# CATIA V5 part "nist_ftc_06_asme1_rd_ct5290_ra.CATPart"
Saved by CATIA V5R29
Part number: NIST PMI FTC 06 ASME1
Revision: D
Description: NIST PMI test model downloaded from http://go.usa.gov/mGVm
Bounding box of the stored display mesh (mm): x -152.4 to 152.4, y 0 to 97.79, z -247.65 to 0
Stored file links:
  E:\users\dgn\TPS V5\Import-export annotations\Step\PMI representation 2015\NIST UC\FTC\R29\nist_ftc_06_asme1_ct5240_rd - V5R29.CATPart
  E:\users\dgn\TPS V5\Import-export annotations\Step\PMI representation 2015\NIST UC\nist_ftc_06_asme1_ct5240_rd.CATPart
  E:\users\dgn\TPS V5\Import-export annotations\Step\PMI representation 2015\NIST UC\CVDHoleParallelCountersink_1_TAG.CATPart
  E:\users\dgn\TPS V5\Import-export annotations\Step\PMI representation 2015\NIST UC\TS_CounterboredHole.CATPart
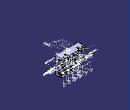
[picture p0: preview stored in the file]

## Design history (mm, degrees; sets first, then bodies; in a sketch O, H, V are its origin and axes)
TTRSSet1
f4a2d38f3ddc11d3a929006094b99c4b_11 "CATTPSSet"
Set1 "Geom_for_MBD_A_notes"
  Plane1: type Equation, A -0.57735, B -0.57735, C 0.57735, Length 229.55, RefPoint vertex [face of Pad1 from Sketch12.L1 | face of Pad1 from Sketch12.L2 | end face of Pad1], RefAxis AxisSystem5
Set2 "MBD_A"
  AxisSystem1 "F1": origin (108.585, 50.8, -209.55), X (-1, 0, 0), Y (0, 1, 0), Z (0, 0, -1)
  AxisSystem2 "F2": origin (36.195, 50.8, -209.55), X (-1, 0, 0), Y (0, 1, 0), Z (0, 0, -1)
  AxisSystem3 "F3": origin (-36.195, 50.8, -209.55), X (-1, 0, 0), Y (0, 1, 0), Z (0, 0, -1)
  AxisSystem4 "F4": origin (-108.585, 50.8, -209.55), X (-1, 0, 0), Y (0, 1, 0), Z (0, 0, -1)
  AxisSystem5 "EAB": origin (0, 0, -209.55), X (-1, 0, 0), Y (0, 0, 1), Z (0, 1, 0)
Set3 "MBD_C"
  AxisSystem6 "DCJ": origin (82.55, 31.75, 0), X (1, 0, 0), Y (0, 0, -1), Z (0, 1, 0)
  AxisSystem7 "DCK": origin (-82.55, 31.75, 0), X (1, 0, 0), Y (0, 0, -1), Z (0, 1, 0)
  AxisSystem8 "DG": origin (76.2, 31.75, -158.75), X (0, 0, -1), Y (-1, 0, 0), Z (0, 1, 0)
  AxisSystem9 "DH": origin (-76.2, 31.75, -158.75), X (0, 0, -1), Y (-1, 0, 0), Z (0, 1, 0)
  Sketch1 on face of Pocket1 from Sketch15.L6, origin (-87.885, 40.9814, 0), H (-0.4226, -0.9063, 0), V (0, 0, 1)
    line L1 (-45.8598, -31.75) -> (-45.8598, 0)
    point P1 (-45.8598, -31.75)
    reference projected point E1 (-45.8598, -31.75) from Sketch10.P5
    vertical: L1 V
    coincidence: P1 E1
  Sketch2 on face of RectPattern2, origin (87.885, 40.9814, 0), H (-0.4226, 0.9063, 0), V (0, 0, 1)
    line L1 (45.8598, -31.75) -> (45.8598, 0)
    point P1 (45.8598, -31.75)
    reference projected point E1 (45.8598, -31.75) from Sketch9.P6
    vertical: L1 V
    coincidence: P1 E1
  Sketch3 on face of RectPattern2, origin (47.7271, -22.2555, 0), H (-0.4226, -0.9063, 0), V (0, 0, 1)
    line L1 (-115.6341, -31.75) -> (-115.6341, 0)
    point P1 (-115.6341, -31.75)
    reference projected point E1 (-115.6341, -31.75) from Sketch9.P5
    vertical: L1 V
    coincidence: P1 E1
  Sketch4 on Plane6, origin (0, 66.04, 0), H (-1, 0, 0), V (0, 0, 1)
    circle A1 centre (76.2, -158.75) radius 12.7
    point P1 (76.2, -158.75)
    reference projected point E1 (76.2, -158.75) from axis of face of RectPattern6
    circle A2 centre (-76.2, -158.75) radius 12.7
    point P2 (-76.2, -158.75)
    reference projected point E2 (-76.2, -158.75) from axis of face of Hole3
    radius A1 = 12.7
    radius A2 = 12.7
    coincidence: E1 P1, E2 P2
  Sketch5 on face of RectPattern2, origin (47.7271, -22.2555, 0), H (-0.4226, -0.9063, 0), V (0, 0, 1)
    projected line E1 (-132.4556, 0) -> (-97.4233, 0) from edge [face of RectPattern2 | face of Pad1 from Sketch12.L1]
    projected line E2 (-132.4556, -31.75) -> (-97.4233, -31.75) from edge [face of Pad1 from Sketch12.L7 | face of RectPattern2]
    line L1 (-97.4233, 0) -> (-115.6341, 0)
    point P5 (-114.9395, 0)
    line L2 (-115.6341, -31.75) -> (-97.4233, -31.75)
    point P6 (-115.6341, -31.75)
    line L3 (-97.4233, 0) -> (-97.4233, -31.75)
    line L4 (-115.6341, 0) -> (-115.6341, -31.75)
    reference projected line E3 (-115.6341, -31.75) -> (-115.6341, 0) from Sketch3
    midpoint: P5 E1
    horizontal: L1 H, L2 H
    coincidence: P6 E2, E3 L4
    vertical: L3 V, L4 V
  Sketch6 on face of RectPattern2, origin (87.885, 40.9814, 0), H (-0.4226, 0.9063, 0), V (0, 0, 1)
    projected line E1 (62.6813, 0) -> (27.6491, 0) from edge [face of Pad1 from Sketch12.L1 | face of RectPattern2]
    projected line E2 (45.8598, 0) -> (27.6491, 0) from edge [face of Pad1 from Sketch12.L1 | face of RectPattern2]
    projected line E3 (27.6491, -31.75) -> (27.6491, 0) from edge [face of RectPattern2 | face of RectPattern2]
    projected line E4 (27.6491, -31.75) -> (62.6813, -31.75) from edge [face of Pad1 from Sketch12.L7 | face of RectPattern2]
    projected line E5 (27.6491, -31.75) -> (45.8598, -31.75) from edge [face of Pad1 from Sketch12.L7 | face of RectPattern2]
    projected line E6 (45.8598, -31.75) -> (45.8598, 0) from Sketch2.L1
  Sketch7 on face of Pocket1 from Sketch15.L6, origin (-87.885, 40.9814, 0), H (-0.4226, -0.9063, 0), V (0, 0, 1)
    projected line E1 (-62.6813, 0) -> (-27.6491, 0) from edge [face of Pocket1 from Sketch15.L6 | face of Pad1 from Sketch12.L1]
    projected line E2 (-45.8598, 0) -> (-27.6491, 0) from edge [face of Pocket1 from Sketch15.L6 | face of Pad1 from Sketch12.L1]
    projected line E3 (-62.6813, -31.75) -> (-27.6491, -31.75) from edge [face of Pad1 from Sketch12.L7 | face of Pocket1 from Sketch15.L6]
    projected line E4 (-45.8598, -31.75) -> (-27.6491, -31.75) from edge [face of Pad1 from Sketch12.L7 | face of Pocket1 from Sketch15.L6]
    projected line E5 (-27.6491, -31.75) -> (-27.6491, 0) from edge [face of Pocket1 from Sketch15.L5 | face of Pocket1 from Sketch15.L6]
    projected line E6 (-45.8598, -31.75) -> (-45.8598, 0) from Sketch1.L1
  Sketch8 on face of Pocket1 from Sketch15.L1, origin (-47.7271, -22.2555, 0), H (-0.4226, 0.9063, 0), V (0, 0, 1)
    projected line E1 (97.4233, -31.75) -> (132.4556, -31.75) from edge [face of Pad1 from Sketch12.L7 | face of Pocket1 from Sketch15.L1]
    projected line E2 (97.4233, -31.75) -> (115.6341, -31.75) from edge [face of Pad1 from Sketch12.L7 | face of Pocket1 from Sketch15.L1]
    projected line E3 (97.4233, -31.75) -> (97.4233, 0) from edge [face of Pocket1 from Sketch15.L1 | face of Pocket1 from Sketch15.L2]
    projected line E4 (132.4556, 0) -> (97.4233, 0) from edge [face of Pad1 from Sketch12.L1 | face of Pocket1 from Sketch15.L1]
    projected line E5 (115.6341, 0) -> (97.4233, 0) from edge [face of Pad1 from Sketch12.L1 | face of Pocket1 from Sketch15.L1]
    projected line E6 (115.6341, -31.75) -> (115.6341, 0) from Sketch11.L1
    construction line L1 through (0, 0) direction (0, 1)
  Sketch9 on face of Pad1 from Sketch12.L7, origin (0, 0, -31.75), H (1, 0, 0), V (0, -1, 0)
    projected line E1 (103.7053, -97.79) -> (88.9, -66.04) from edge [face of Pad1 from Sketch12.L7 | face of RectPattern2]
    projected line E2 (76.2, -66.04) -> (61.3947, -97.79) from edge [face of Pad1 from Sketch12.L7 | face of RectPattern2]
    line L1 (88.9, -66.04) -> (76.2, -66.04)
    line L2 (96.5962, -82.5446) -> (68.5038, -82.5446)
    point P5 (96.5962, -82.5446)
    point P6 (68.5038, -82.5446)
    point P7 (96.5962, -82.5446)
    point P8 (68.5038, -82.5446)
    length L2 = 28.0924
    horizontal: L1 H, L2 H
    coincidence: P5 E1, P6 E2, P7 P5, P8 P6
  Sketch10 on face of Pad1 from Sketch12.L7, origin (0, 0, -31.75), H (1, 0, 0), V (0, -1, 0)
    projected line E1 (-61.3947, -97.79) -> (-76.2, -66.04) from edge [face of Pad1 from Sketch12.L7 | face of Pocket1 from Sketch15.L6]
    projected line E2 (-88.9, -66.04) -> (-103.7053, -97.79) from edge [face of Pad1 from Sketch12.L7 | face of Pocket1 from Sketch15.L1]
    line L1 (-76.2, -66.04) -> (-88.9, -66.04)
    line L2 (-68.5038, -82.5446) -> (-96.5962, -82.5446)
    point P5 (-68.5038, -82.5446)
    point P6 (-96.5962, -82.5446)
    point P7 (-68.5038, -82.5446)
    point P8 (-96.5962, -82.5446)
    length L2 = 28.0924
    horizontal: L1 H, L2 H
    coincidence: P5 E1, P7 P5, P6 E2, P8 P6
  Sketch11 on face of Pocket1 from Sketch15.L1, origin (-47.7271, -22.2555, 0), H (-0.4226, 0.9063, 0), V (0, 0, 1)
    line L1 (115.6341, -31.75) -> (115.6341, 0)
    point P1 (115.6341, -31.75)
    reference projected point E1 (115.6341, -31.75) from Sketch10.P6
    vertical: L1 V
    coincidence: P1 E1
Set4 "MBD_A_B_C"
  AxisSystem10 "DBC": origin (0, 31.75, 0), X (1, 0, 0), Y (0, 0, -1), Z (0, 1, 0)
  AxisSystem11 "ABC": origin (0, 0, 0), X (1, 0, 0), Y (0, 0, -1), Z (0, 1, 0)
Set5
  Plane2: type Offset, RefPlane xy-plane, Offset 247.65, reversed
  Plane3: type Offset, RefPlane zx-plane, Offset 46.99
  Plane4: type Offset, RefPlane yz-plane, Offset 76.2
  Plane5: type Offset, RefPlane yz-plane, Offset 114.3
  Point1: type OnCurve, Support edge [face of Pad1 from Sketch12.L7 | face of Pocket1 from Sketch15.L1], Length 18.2093
  Point2: type OnCurve, Support edge [face of Pad1 from Sketch12.L7 | face of Pocket1 from Sketch15.L6], Length 18.2093
  Point3: type OnCurve, Support edge [face of Pad1 from Sketch12.L7 | face of RectPattern2], Length 18.2093
  Point4: type OnCurve, Support edge [face of Pad1 from Sketch12.L7 | face of RectPattern2], Length 18.2093
  Plane6: type Offset, RefPlane zx-plane, Offset 66.04
  Plane7: type Angle, RefPlane xy-plane, Direction edge [face of Pad1 from Sketch12.L2 | face of Pad1 from Sketch12.L1], Angle 45
  Point5: type OnCurve, Support edge [face of Pad1 from Sketch12.L2 | face of Pad1 from Sketch12.L1], Length 152.4
  Point6: type OnPlane, Support face of Pad1 from Sketch12.L6, H 0, V 0, Direction (-1, 0, 0)
  Point7: type OnCurve, Support edge [face of Fillet1 | face of Pad1 from Sketch12.L6], RefPoint {extremum Reference edge [face of Fillet1 | face of Pad1 from Sketch12.L6], Direction (1, 2, 3)}, Length 65.977
  Point8: type OnCurve, Support edge [face of Fillet1 | face of Pad1 from Sketch12.L6], RefPoint {extremum Reference edge [face of Fillet1 | face of Pad1 from Sketch12.L6], Direction (1, 2, 3)}, Length 65.9892
  Point9: type OnPlane, Support face of Pad1 from Sketch12.L1, H 82.55, V 31.75, Direction (1, 0, 0)
  Point10: type OnPlane, Support face of Pad1 from Sketch12.L1, H -82.55, V 31.75, Direction (1, 0, 0)
  Plane8: type Offset, RefPlane face of Pad1 from Sketch12.L2, Offset 82.55
  Plane9: type Offset, RefPlane face of Pad1 from Sketch12.L2, Offset 66.04
  Point11: type OnSurface, Support face of Fillet1, Length 0, Direction (-0.9567, 0.021, -0.2904)
  Plane10: type Offset, RefPlane face of Pad1 from Sketch12.L1, Offset 107.95
  Point12: type OnPlane, Support face of Pad1 from Sketch12.L6, H -76.2, V -158.75, Direction (-1, 0, 0)
  Point13: type OnPlane, Support face of Pad1 from Sketch12.L6, H 76.2, V -158.75, Direction (-1, 0, 0)
  Point14: type OnPlane, Support face of Pad1 from Sketch12.L2, H 0, V -209.55, Direction (1, 0, 0)
  Plane11: type Offset, RefPlane face of Pad1 from Sketch12.L8, Offset 0, reversed
  Point15 to Point18: stored without definition
Body1 (main body)
  Sketch12 on yz-plane, origin (0, 0, 0), H (0, 1, 0), V (0, 0, 1)
    point P1 (97.79, 0)
    line L1 (97.79, 0) -> (0, 0)
    line L2 (0, 0) -> (0, -234.95)
    line L3 (0, -234.95) -> (50.8, -234.95)
    line L4 (50.8, -234.95) -> (50.8, -209.55)
    line L5 (50.8, -209.55) -> (31.75, -209.55)
    line L6 (31.75, -209.55) -> (31.75, -31.75)
    line L7 (31.75, -31.75) -> (97.79, -31.75)
    line L8 (97.79, -31.75) -> (97.79, 0)
    length L2 = 234.95
    distance L1 L5 = 209.55
    distance L1 L7 = 31.75
    distance L2 L6 = 31.75
    distance L4 L2 = 50.8
    distance L2 L8 = 97.79
    coincidence: P1 H
    horizontal: L1 H, L3 H, L5 H, L7 H
    vertical: L2 V, L4 V, L6 V, L8 V
  Pad1: profile Sketch12, direction (1, 0, 0), length 152.4, mirrored extent
  Sketch13 on yz-plane, origin (0, 0, 0), H (0, 1, 0), V (0, 0, 1)
    line L1 (97.79, -31.75) -> (46.99, -133.35)
    point P1 (97.79, -31.75)
    point P2 (46.99, -133.35)
    line L2 (46.99, -133.35) -> (31.75, -133.35)
    point P3 (31.75, -133.35)
    reference projected point E1 (97.79, -31.75) from vertex [face of Pad1 from Sketch12.L8 | end face of Pad1 | face of Pad1 from Sketch12.L7]
    reference projected point E2 (97.79, -31.75) from vertex [face of Pad1 from Sketch12.L8 | end face of Pad1 | face of Pad1 from Sketch12.L7]
    reference projected line E3 (31.75, -31.75) -> (97.79, -31.75) from edge [face of Pad1 from Sketch12.L7 | end face of Pad1]
    reference projected line E4 (97.79, -31.75) -> (97.79, 0) from edge [face of Pad1 from Sketch12.L8 | end face of Pad1]
    reference intersected line E5 (31.75, -31.75) -> (31.75, -209.55) from face of Pad1 from Sketch12.L6
    distance E3 L2 = 101.6
    distance P2 E4 = 50.8
    coincidence: E1 L1, E2 P1, E5 P3
  Stiffener1: ExtendedProfile Sketch13, ThicknessTop 0, ThicknessValue 25.4
  Sketch14 on Plane2, origin (0, 0, -247.65), H (1, 0, 0), V (0, 1, 0)
    circle A1 centre (108.585, 50.8) radius 22.225
    point P1 (108.585, 50.8)
    reference projected line E1 (-152.4, 0) -> (152.4, 0) from edge [face of Pad1 from Sketch12.L3 | face of Pad1 from Sketch12.L2]
    reference intersected line E2 through (152.4, 0) direction (0, 1) from end face of Pad1
    distance P1 E1 = 50.8
    radius A1 = 22.225
    distance E2 P1 = 43.815
  Pad2: profile Sketch14, direction (0, 0, 1), length 38.1
  RectPattern1: of Pad2, direction 1 instances 4, spacing 72.39, along edge [face of Pad1 from Sketch12.L4 | face of Pad1 from Sketch12.L3] reversed
  Sketch15 on face of Pad1 from Sketch12.L7, origin (0, 0, -31.75), H (1, 0, 0), V (0, -1, 0)
    line L1 (-103.7053, -97.79) -> (-88.9, -66.04)
    point P1 (-88.9, -66.04)
    line L2 (-88.9, -66.04) -> (-88.9, -52.07)
    line L3 (-88.9, -52.07) -> (-76.2, -52.07)
    reference intersected line E1 (-152.4, 0) -> (152.4, 0) from face of Pad1 from Sketch12.L2
    axis line L4 (-82.55, -52.07) -> (-82.55, -133.5251)
    reference intersected line E2 (-152.4, 0) -> (152.4, 0) from face of Pad1 from Sketch12.L2
    point P7 (-76.2, -66.04)
    line L5 (-76.2, -66.04) -> (-76.2, -52.07)
    line L6 (-61.3947, -97.79) -> (-76.2, -66.04)
    reference intersected line E3 through (0, 0) direction (0, 1) from yz-plane
    projected line E4 (-152.4, -97.79) -> (-12.7, -97.79) from edge [face of Pad1 from Sketch12.L8 | face of Pad1 from Sketch12.L7]
    projected line E5 (-103.7053, -97.79) -> (-61.3947, -97.79) from edge [face of Pad1 from Sketch12.L8 | face of Pad1 from Sketch12.L7]
    distance E1 L3 = 52.07
    length L3 = 12.7
    distance L2 L4 = 6.35
    distance E2 P1 = 66.04
    distance E2 P7 = 66.04
    distance L5 L4 = 6.35
    angle L1 L6 = 50
    distance E3 L4 = 82.55
    angle L1 L4 = 25
  Pocket1: profile Sketch15, direction (0, 0, 1), through (limit type 6)
  RectPattern2: of Pocket1, direction 1 instances 2, spacing 165.1, along edge [face of Pad1 from Sketch12.L8 | face of Pad1 from Sketch12.L7]
  Sketch16 on Plane3, origin (0, 46.99, 0), H (0, 0, 1), V (1, 0, 0)
    circle A1 centre (-158.75, 76.2) radius 15.875
    point P1 (-158.75, 76.2)
    reference projected line E1 (0, -152.4) -> (0, 152.4) from edge [face of Pad1 from Sketch12.L1 | face of Pad1 from Sketch12.L8]
    reference intersected line E2 through (0, 0) direction (-1, 0) from yz-plane
    radius A1 = 15.875
    distance E1 P1 = 158.75
    distance E2 P1 = 76.2
  Pad3: profile Sketch16, direction (0, -1, 0), up to face of Pad1 from Sketch12.L6
  Sketch17 on Plane4, origin (76.2, 0, 0), H (0, 1, 0), V (0, 0, 1)
    axis line L1 (47.3647, -158.75) -> (174.207, -158.75)
    reference intersected line E1 (0, 0) -> (97.79, 0) from face of Pad1 from Sketch12.L1
    point P3 (46.99, -174.625)
    line L2 (46.99, -174.625) -> (85.09, -168.275)
    line L3 (85.09, -168.275) -> (85.09, -158.75)
    line L4 (85.09, -158.75) -> (46.99, -158.75)
    reference intersected line E2 (0, -234.95) -> (0, 0) from face of Pad1 from Sketch12.L2
    projected line E3 (46.99, -142.875) -> (46.99, -174.625) from edge [face of Pad3 from Sketch16.A1 | start face of Pad3]
    projected line E4 (46.99, -158.75) -> (46.99, -174.625) from edge [face of Pad3 from Sketch16.A1 | start face of Pad3]
    point P7 (46.99, -174.625)
    distance E1 L1 = 158.75
    distance L3 E2 = 85.09
    length L3 = 9.525
    coincidence: P3 P7, L1 L4
  Shaft1: profile Sketch17, axis Sketch17.L1, angle 360
  Sketch18 on Plane5, origin (114.3, 0, 0), H (0, 1, 0), V (0, 0, 1)
    axis line L1 (-156.5, -107.95) -> (163.5, -107.95)
    arc A1 centre (63.5, -107.95) radius 15.875 from (79.375, -107.95) to (47.625, -107.95) ccw
    point P3 (63.5, -107.95)
    reference projected line E1 (97.79, 0) -> (0, 0) from edge [face of Pad1 from Sketch12.L1 | end face of Pad1]
    reference projected line E2 (0, 0) -> (0, -234.95) from edge [face of Pad1 from Sketch12.L2 | end face of Pad1]
    distance P3 E1 = 107.95
    distance E2 P3 = 63.5
    radius A1 = 15.875
    coincidence: P3 L1
  Shaft2: profile Sketch18, axis Sketch18.L1, angle 360
  Sketch19 on face of Pad1 from Sketch12.L6, origin (0, 31.75, 0), H (-1, 0, 0), V (0, 0, 1)
    circle A1 centre (-114.3, -107.95) radius 11.43
    point P1 (-114.3, -107.95)
    reference intersected line E1 (-152.4, 0) -> (152.4, 0) from face of Pad1 from Sketch12.L1
    reference intersected line E2 through (0, 0) direction (0, -1) from yz-plane
    distance P1 E1 = 107.95
    distance P1 E2 = 114.3
    radius A1 = 11.43
  Pad4: profile Sketch19, direction (0, 1, 0), up to face of Shaft2 from Sketch18.A1
  Sketch20 on face of Pad1 from Sketch12.L7, origin (129.0197, 80.9562, -31.75), H (1, 0, 0), V (0, -1, 0)
    point P1 (-2.0197, 2.2162)
    reference intersected line E1 through (-129.0197, 0) direction (0, 1) from yz-plane
    reference intersected line E2 (23.3803, -16.8338) -> (-281.4197, -16.8338) from face of Pad1 from Sketch12.L8
    distance E1 P1 = 127
    distance P1 E2 = 19.05
  Hole1: placed by Sketch20, at (127, 78.74, -31.75) direction (0, 0, 1), diameter 14.2875, through (limit type 6), counterbore diameter 20.6375, counterbore depth 14.2875
  RectPattern3: of Hole1, direction 1 instances 2, spacing 254, along edge [face of Pad1 from Sketch12.L8 | face of Pad1 from Sketch12.L7] reversed
  Sketch21 on face of Pad1 from Sketch12.L6, origin (123.0782, 31.75, -62.8696), H (1, 0, 0), V (0, 0, -1)
    point P1 (10.2718, -5.7196)
    reference projected line E1 (-275.4782, -62.8696) -> (29.3218, -62.8696) from edge [face of Pad1 from Sketch12.L1 | face of Pad1 from Sketch12.L8]
    reference intersected line E2 through (-123.0782, 0) direction (0, 1) from yz-plane
    distance E1 P1 = 57.15
    distance E2 P1 = 133.35
  Hole2: placed by Sketch21, at (133.35, 31.75, -57.15) direction (0, -1, 0), diameter 10.541, through (limit type 6), counterbore diameter 15.875, counterbore depth 12.7
  RectPattern4: of Hole2, direction 1 instances 2, spacing 266.7, along edge [face of Pad1 from Sketch12.L8 | face of Pad1 from Sketch12.L7] reversed, direction 2 instances 2, spacing 127, along edge [face of Pad1 from Sketch12.L6 | end face of Pad1] reversed
  RectPattern5: of Pad3, Sketch16, Shaft1, Sketch17, direction 1 instances 2, spacing 152.4, along edge [face of Pad1 from Sketch12.L8 | face of Pad1 from Sketch12.L7] reversed, direction 2 instances 2, spacing 127
  Sketch22 on face of Shaft1 from Sketch17.L3, origin (76.2, 85.09, -158.75), H (1, 0, 0), V (0, 0, -1)
    point P1 (0, 0)
    coincidence: P1 O
  Hole3: placed by Sketch22, at (76.2, 85.09, -158.75) direction (0, -1, 0), diameter 6.35, depth 12.7, V-bottom angle 118
  RectPattern6: of Hole3, direction 1 instances 2, spacing 152.4, along edge [face of Pad1 from Sketch12.L4 | face of Pad1 from Sketch12.L3] reversed, direction 2 instances 2, spacing 127
  Fillet1: radius 3.175, on edge [face of Pad1 from Sketch12.L7 | face of Pad1 from Sketch12.L6] (x2); edge [face of Stiffener1 | face of Pad1 from Sketch12.L7]; edge [face of Pad1 from Sketch12.L6 | face of Stiffener1]; edge [face of Stiffener1 from Sketch13.L2 | face of Pad1 from Sketch12.L6]; edge [face of Stiffener1 | face of Pad1 from Sketch12.L6]; edge [face of Pad1 from Sketch12.L7 | face of Stiffener1]; edge [face of Pad1 from Sketch12.L6 | face of RectPattern5]; edge [face of Pad1 from Sketch12.L6 | face of Pad3 from Sketch16.A1]; edge [face of Pad1 from Sketch12.L6 | face of RectPattern1]; edge [face of Pad1 from Sketch12.L4 | face of Pad2 from Sketch14.A1]; edge [face of Pad2 from Sketch14.A1 | face of Pad1 from Sketch12.L4]; edge [face of RectPattern1 | face of Pad1 from Sketch12.L4] (x3); edge [face of Pad1 from Sketch12.L4 | face of RectPattern1] (x3)
  Sketch23 on face of Pad1 from Sketch12.L8, origin (0, 97.79, 0), H (-1, 0, 0), V (0, 0, 1)
    arc A1 centre (0, -15.875) radius 12.7 from (0, -28.575) to (0, -3.175) ccw
    point P1 (0, -15.875)
    reference intersected line E1 through (0, 0) direction (0, -1) from yz-plane
    reference intersected line E2 (152.4, -31.75) -> (-152.4, -31.75) from face of Pad1 from Sketch12.L7
    line L1 (0, -3.175) -> (0, -28.575)
    radius A1 = 12.7
    distance E2 P1 = 15.875
    coincidence: E1 P1, P1 L1
    vertical: L1 V
  Fillet2: radius 12.7, on edge [start face of Pad1 | face of Pad1 from Sketch12.L8]; edge [face of Pad1 from Sketch12.L8 | end face of Pad1]
  Groove1: profile Sketch23, axis Sketch23.L1, angle 360
  Sketch24 on Plane10, origin (0, 97.79, -107.95), H (0, 1, 0), V (1, 0, 0)
    line L1 (-66.04, -114.3) -> (-18.415, -114.3)
    point P1 (-162.8215, -114.3)
    point P2 (-2.54, -114.3)
    line L2 (-66.04, -114.3) -> (-66.04, -125.73)
    line L3 (-66.04, -125.73) -> (-45.3068, -125.73)
    arc A1 centre (-34.29, -114.3) radius 15.875 from (-45.3068, -125.73) to (-18.415, -114.3) ccw
    point P5 (-34.29, -114.3)
    reference intersected line E1 (-66.04, 152.4) -> (-66.04, -152.4) from face of Pad1 from Sketch12.L6
    reference intersected line E2 through (0, 0) direction (-1, 0) from yz-plane
    reference intersected line E3 (-97.79, -152.4) -> (-97.79, 152.4) from face of Pad1 from Sketch12.L2
    radius A1 = 15.875
    distance E2 L1 = 114.3
    distance L1 L3 = 11.43
    distance P5 E3 = 63.5
    horizontal: L1 H, L3 H
    vertical: L2 V
    coincidence: E1 L2, P1 L1, L1 P5
  Shaft3: profile Sketch24, axis Sketch24.L1, angle 360
  Fillet3: radius 3.175, on edge [face of Pad4 from Sketch19.A1 | face of Shaft2 from Sketch18.A1]; edge [face of Pad1 from Sketch12.L6 | face of Pad4 from Sketch19.A1]
  Fillet4: radius 3.175, on edge [face of Shaft3 from Sketch24.A1 | face of Shaft3 from Sketch24.L3]; edge [face of Shaft3 from Sketch24.L3 | face of Pad1 from Sketch12.L6]
  Sketch25 "Main View" on face of Pad1 from Sketch12.L3, origin (0, 0, -234.95), H (-1, 0, 0), V (0, 1, 0)
    point P1 (-27.9401, 6.35)
    point P2 (-14.4332, 7.6694)
    point P3 (-8.1701, 9.8671)
    point P4 (-3.0267, 10.5457)
    point P5 (-1.9341, 9.4532)
    point P6 (-24.8376, 6.35)
    point P7 (-27.9401, 6.35)
    point P8 (-24.8376, 17.5935)
    point P9 (-24.8376, 6.35)
    point P10 (-23.9004, 17.959)
    point P11 (-24.8376, 17.5935)
    point P12 (-14.4332, 7.6694)
    point P13 (-23.9004, 17.959)
    point P14 (-8.1701, 21.35)
    point P15 (-8.1701, 9.8671)
    point P16 (-11.3024, 21.35)
    point P17 (-8.1701, 21.35)
    point P18 (-11.3024, 9.9419)
    point P19 (-11.3024, 21.35)
    point P20 (-12.02, 9.6257)
    point P21 (-11.3024, 9.9419)
    point P22 (-22.2849, 20.7261)
    point P23 (-12.02, 9.6257)
    point P24 (-22.2849, 20.7261)
    point P25 (-27.9401, 18.5121)
    point P26 (-27.9401, 6.35)
    point P27 (-27.9401, 18.5121)
    point P28 (-3.0267, 21.35)
    point P29 (-6.159, 21.35)
    point P30 (-3.0267, 10.5457)
    point P31 (-3.0267, 21.35)
    point P32 (12.7773, 9.4532)
    point P33 (-1.9341, 9.4532)
    point P34 (12.7773, 9.4532)
    point P35 (12.7198, 12.2696)
    point P36 (3.668, 12.2696)
    point P37 (12.7198, 12.2696)
    point P38 (3.3241, 21.35)
    point P39 (3.668, 12.2696)
    point P40 (28.9273, 21.35)
    point P41 (3.3241, 21.35)
    point P42 (28.9273, 18.189)
    point P43 (28.9273, 21.35)
    point P44 (22.5181, 18.189)
    point P45 (28.9273, 18.189)
    point P46 (22.5181, 6.35)
    point P47 (22.5181, 18.189)
    point P48 (19.4156, 6.35)
    point P49 (22.5181, 6.35)
    point P50 (19.4156, 18.189)
    point P51 (19.4156, 6.35)
    point P52 (3.7255, 18.189)
    point P53 (19.4156, 18.189)
    point P54 (3.7255, 18.189)
    point P55 (3.6105, 15.3729)
    point P56 (13.2373, 15.3729)
    point P57 (3.6105, 15.3729)
    point P58 (13.2373, 6.35)
    point P59 (13.2373, 15.3729)
    point P60 (-1.9632, 6.35)
    point P61 (13.2373, 6.35)
    point P62 (-6.159, 10.5457)
    point P63 (-1.9632, 6.35)
    point P64 (-6.159, 21.35)
    point P65 (-6.159, 10.5457)
    line L1 (-6.159, 21.35) -> (-6.159, 10.5457)
    arc A1 centre (-1.9632, 10.5457) radius 4.1957 from (-6.159, 10.5457) to (-1.9632, 6.35) ccw
    line L2 (-1.9632, 6.35) -> (13.2373, 6.35)
    arc A2 centre (12.5188, 10.8615) radius 4.5683 from (13.2373, 6.35) to (13.2373, 15.3729) ccw
    line L3 (13.2373, 15.3729) -> (3.6105, 15.3729)
    arc A3 centre (3.6105, 16.7833) radius 1.4104 from (3.7255, 18.189) to (3.6105, 15.3729) ccw
    line L4 (3.7255, 18.189) -> (19.4156, 18.189)
    line L5 (19.4156, 18.189) -> (19.4156, 6.35)
    line L6 (19.4156, 6.35) -> (22.5181, 6.35)
    line L7 (22.5181, 6.35) -> (22.5181, 18.189)
    line L8 (22.5181, 18.189) -> (28.9273, 18.189)
    line L9 (28.9273, 18.189) -> (28.9273, 21.35)
    line L10 (28.9273, 21.35) -> (3.3241, 21.35)
    arc A4 centre (3.3241, 16.8033) radius 4.5467 from (3.3241, 21.35) to (3.668, 12.2696) ccw
    line L11 (3.668, 12.2696) -> (12.7198, 12.2696)
    arc A5 centre (12.5971, 10.8583) radius 1.4166 from (12.7773, 9.4532) to (12.7198, 12.2696) ccw
    line L12 (12.7773, 9.4532) -> (-1.9341, 9.4532)
    line L13 (-3.0267, 10.5457) -> (-3.0267, 21.35)
    line L14 (-3.0267, 21.35) -> (-6.159, 21.35)
    line L15 (-27.9401, 6.35) -> (-27.9401, 18.5121)
    arc A6 centre (-24.6791, 18.5121) radius 3.261 from (-22.2849, 20.7261) to (-27.9401, 18.5121) ccw
    line L16 (-22.2849, 20.7261) -> (-12.02, 9.6257)
    arc A7 centre (-11.7156, 9.9072) radius 0.4146 from (-12.02, 9.6257) to (-11.3024, 9.9419) ccw
    line L17 (-11.3024, 9.9419) -> (-11.3024, 21.35)
    line L18 (-11.3024, 21.35) -> (-8.1701, 21.35)
    line L19 (-8.1701, 21.35) -> (-8.1701, 9.8671)
    line L20 (-14.4332, 7.6694) -> (-23.9004, 17.959)
    arc A8 centre (-24.2977, 17.5935) radius 0.5399 from (-23.9004, 17.959) to (-24.8376, 17.5935) ccw
    line L21 (-24.8376, 17.5935) -> (-24.8376, 6.35)
    line L22 (-24.8376, 6.35) -> (-27.9401, 6.35)
    arc A9 centre (-1.9341, 10.5457) radius 1.0926 from (-3.0267, 10.5457) to (-1.9341, 9.4532) ccw
    arc A10 centre (-11.6873, 9.8671) radius 3.5171 from (-14.4332, 7.6694) to (-8.1701, 9.8671) ccw
    distance P1 H = 6.35
    distance P1 V = 27.94
    fix: P2, P3, P4, P5, P6, P8, P9, P10, P11, P12, P13, P14, P15, P16, P17, P18, P19, P20, P21, P22, P23, P24, P25, P27, P28, P29, P30, P31, P32, P33, P34, P35, P36, P37, P38, P39, P40, P41, P42, P43, P44, P45, P46, P47, P48, P49, P50, P51, P52, P53, P54, P55, P56, P57, P58, P59, P60, P61, P62, P63, P64, P65, P1, P7, L1, A1, L2, A2, L3, A3, L4, L5, L6, L7, L8, L9, L10, A4, L11, A5, L12, L13, L14, L15, A6, L16, A7, L17, L18, L19, L20, A8, L21, L22, A9, A10, P26
  Pocket2: profile Sketch25, direction (0, 0, 1), length 2.54
  UdfFeature1 "Counterbored Hole": UdfShapeIn Pocket2, UdfInputSpec1 AxisSystem12, UdfInputSpec2 Project1, UdfInputSpec3 Intersect1, DB 7.1374, T 40.64 {= Body2.Offset + (Sketch26.length(L2) * (Body2.Offset / Body2.Offset))}, DFS 10.16, TFS 10.414
  UdfFeature2 "Counterbored Hole": UdfShapeIn UdfFeature1, UdfInputSpec1 AxisSystem14, UdfInputSpec2 Project2, UdfInputSpec3 Intersect2, DB 7.1374, T 40.64 {= Body3.Offset + (Sketch27.length(L2) * (Body3.Offset / Body3.Offset))}, DFS 10.16, TFS 10.414
  UdfFeature3 "Counterbored Hole": UdfShapeIn UdfFeature2, UdfInputSpec1 AxisSystem16, UdfInputSpec2 Project3, UdfInputSpec3 Intersect3, DB 7.1374, T 40.64 {= Body4.Offset + (Sketch28.length(L2) * (Body4.Offset / Body4.Offset))}, DFS 10.16, TFS 10.414
  UdfFeature4 "Counterbored Hole": UdfShapeIn UdfFeature3, UdfInputSpec1 AxisSystem18, UdfInputSpec2 Project4, UdfInputSpec3 Intersect4, DB 7.1374, T 40.64 {= Body5.Offset + (Sketch29.length(L2) * (Body5.Offset / Body5.Offset))}, DFS 10.16, TFS 10.414
Body2 "UDF_Body"
  AxisSystem12 "MainAxisSystem": origin (108.585, 50.8, -250.19), X (-0.9916, -0.1291, 0), Y (-0.1291, 0.9916, 0), Z (0, 0, -1)
  Project1 "Project": ToProject vertex [YZ plane of AxisSystem12 | ZX plane of AxisSystem12 | XY plane of AxisSystem12], Support face of RectPattern1
  Intersect1 "Intersect": ToIntersect1 edge [ZX plane of AxisSystem12 | YZ plane of AxisSystem12], ToIntersect2 face of RectPattern1
  Sketch26 "MainProfileSketch" on ZX plane of AxisSystem12, origin (108.585, 50.8, -250.19), H (0.9916, 0.1291, 0), V (0, 0, -1)
    axis line L1 (0, 0) -> (0, -40.64)
    line L2 (0, -40.64) -> (3.5687, -40.64)
    point P3 (3.5687, -40.64)
    line L3 (3.5687, -40.64) -> (3.5687, -10.414)
    line L4 (5.08, -2) -> (7.08, 0)
    point P4 (7.08, 0)
    line L5 (7.08, 0) -> (7.08, 0)
    line L6 (7.08, 0) -> (7.08, 0)
    line L7 (7.08, 0) -> (0, 0)
    construction line L8 (7.08, 0) -> (0, 0)
    reference projected line E1 through (0, 0) direction (-1, 0) from edge [XY plane of AxisSystem12 | ZX plane of AxisSystem12]
    reference projected line E2 through (0, 0) direction (-1, 0) from edge [XY plane of AxisSystem12 | ZX plane of AxisSystem12]
    reference projected line E3 through (0, 0) direction (0, 1) from edge [ZX plane of AxisSystem12 | YZ plane of AxisSystem12]
    point P7 (-7.08, 0)
    construction line L9 (-11.04, 3.96) -> (-7.08, 0)
    reference projected line E4 through (0, 0) direction (-1, 0) from edge [XY plane of AxisSystem12 | ZX plane of AxisSystem12]
    line L10 (5.08, -10.414) -> (5.08, -2)
    line L11 (3.5687, -10.414) -> (5.08, -10.414)
    arc A1 centre (5.08, -10.414) radius 0 from (5.08, -10.414) to (5.08, -10.414) ccw
    point P9 (5.08, -10.414)
    reference projected line E5 through (0, 0) direction (-1, 0) from edge [XY plane of AxisSystem12 | ZX plane of AxisSystem12]
    construction line L12 (5.08, -10.414) -> (5.08, -10.414)
    construction line L13 (5.08, -10.414) -> (5.08, -10.414)
    point P10 (5.08, -10.414)
    point P11 (5.08, -10.414)
    point P12 (5.08, -10.414)
    line L14 (3.5687, -40.64) -> (3.5687, -40.64)
    point P13 (3.5687, -40.64)
    point P14 (-3.5687, -40.64)
    point P15 (-3.5687, -40.64)
    construction line L15 (-3.5687, -40.64) -> (-3.5687, -40.64)
    point P18 (5.08, -2)
    reference projected line E6 through (0, 0) direction (-1, 0) from edge [XY plane of AxisSystem12 | ZX plane of AxisSystem12]
    point P19 (0, 30)
    angle L4 L9 = 90
    radius about axis L1 L3 = 3.5687 {= Body2.DB / 2}
    distance E1 L2 = 40.64 {= Body2.Offset + (Sketch26.length(L2) * (Body2.Offset / Body2.Offset))}
    length L8 = 7.08 {= sqrt((Body2.AS_H * Body2.AS_H ) + ((Groove2.top_width / 2 + Groove2.AS_ZR ) * (Groove2.top_width / 2 + Groove2.AS_ZR )))}
    angle L8 L5 = 0 {= atan(Body2.AS_H / (Groove2.top_width / 2 + Groove2.AS_ZR ))}
    distance E6 P18 = 2 (reference)
    distance L5 L11 = 10.414
    radius about axis L10 L1 = 5.08 {= Body2.DFS / 2}
    distance E5 P9 = 10.414 {= Body2.TFS - Body2.R}
    radius about axis P9 L1 = 5.08 {= (Body2.DFS / 2) - Body2.R}
    radius A1 = 0 (reference)
    angle L14 L15 = 0
    distance L2 P3 = 0
    length L2 = 3.5687 (reference)
    distance O P19 = 30
    distance P18 P19 V = 32 {= Sketch26.distance(O P19) + Body2.F1}
    coincidence: E4 L5, L1 E3, P11 P10, P12 L11, P19 L1
    perpendicularity: L1 L7, E2 L6, L12 L10, L13 L11
    symmetry: P4 P7 L1, L4 L9 L1, P3 P14 L1, P13 P15 L1, L14 L15 L1
  Groove2 "MainGroove": profile Sketch26, axis Sketch26.L1, angle 360
  Point19 "LimitingAxisSystemOrigin": type OnCurve, Support edge [ZX plane of AxisSystem12 | YZ plane of AxisSystem12], RefPoint Intersect1, Length 0 {= (Sketch26.length(L2)) * (Body2.Offset / Body2.Offset)}
  AxisSystem13 "LimitingAxisSystem": origin (108.585, 50.8, -209.55), X (-0.9916, -0.1291, 0), Y (0.1168, -0.8972, -0.4259), Z (0.055, -0.4224, 0.9048)
Body3 "UDF_Body"
  AxisSystem14 "MainAxisSystem": origin (36.195, 50.8, -250.19), X (-0.9916, -0.1291, 0), Y (-0.1291, 0.9916, 0), Z (0, 0, -1)
  Project2 "Project": ToProject vertex [YZ plane of AxisSystem14 | ZX plane of AxisSystem14 | XY plane of AxisSystem14], Support face of RectPattern1
  Intersect2 "Intersect": ToIntersect1 edge [ZX plane of AxisSystem14 | YZ plane of AxisSystem14], ToIntersect2 face of RectPattern1
  Sketch27 "MainProfileSketch" on ZX plane of AxisSystem14, origin (36.195, 50.8, -250.19), H (0.9916, 0.1291, 0), V (0, 0, -1)
    axis line L1 (0, 0) -> (0, -40.64)
    line L2 (0, -40.64) -> (3.5687, -40.64)
    point P3 (3.5687, -40.64)
    line L3 (3.5687, -40.64) -> (3.5687, -10.414)
    line L4 (5.08, -2) -> (7.08, 0)
    point P4 (7.08, 0)
    line L5 (7.08, 0) -> (7.08, 0)
    line L6 (7.08, 0) -> (7.08, 0)
    line L7 (7.08, 0) -> (0, 0)
    construction line L8 (7.08, 0) -> (0, 0)
    reference projected line E1 through (0, 0) direction (-1, 0) from edge [XY plane of AxisSystem14 | ZX plane of AxisSystem14]
    reference projected line E2 through (0, 0) direction (-1, 0) from edge [XY plane of AxisSystem14 | ZX plane of AxisSystem14]
    reference projected line E3 through (0, 0) direction (0, 1) from edge [ZX plane of AxisSystem14 | YZ plane of AxisSystem14]
    point P7 (-7.08, 0)
    construction line L9 (-11.04, 3.96) -> (-7.08, 0)
    reference projected line E4 through (0, 0) direction (-1, 0) from edge [XY plane of AxisSystem14 | ZX plane of AxisSystem14]
    line L10 (5.08, -10.414) -> (5.08, -2)
    line L11 (3.5687, -10.414) -> (5.08, -10.414)
    arc A1 centre (5.08, -10.414) radius 0 from (5.08, -10.414) to (5.08, -10.414) ccw
    point P9 (5.08, -10.414)
    reference projected line E5 through (0, 0) direction (-1, 0) from edge [XY plane of AxisSystem14 | ZX plane of AxisSystem14]
    construction line L12 (5.08, -10.414) -> (5.08, -10.414)
    construction line L13 (5.08, -10.414) -> (5.08, -10.414)
    point P10 (5.08, -10.414)
    point P11 (5.08, -10.414)
    point P12 (5.08, -10.414)
    line L14 (3.5687, -40.64) -> (3.5687, -40.64)
    point P13 (3.5687, -40.64)
    point P14 (-3.5687, -40.64)
    point P15 (-3.5687, -40.64)
    construction line L15 (-3.5687, -40.64) -> (-3.5687, -40.64)
    point P18 (5.08, -2)
    reference projected line E6 through (0, 0) direction (-1, 0) from edge [XY plane of AxisSystem14 | ZX plane of AxisSystem14]
    point P19 (0, 30)
    angle L4 L9 = 90
    radius about axis L1 L3 = 3.5687 {= Body3.DB / 2}
    distance E1 L2 = 40.64 {= Body3.Offset + (Sketch27.length(L2) * (Body3.Offset / Body3.Offset))}
    length L8 = 7.08 {= sqrt((Body3.AS_H * Body3.AS_H ) + ((Groove3.top_width / 2 + Groove3.AS_ZR ) * (Groove3.top_width / 2 + Groove3.AS_ZR )))}
    angle L8 L5 = 0 {= atan(Body3.AS_H / (Groove3.top_width / 2 + Groove3.AS_ZR ))}
    distance E6 P18 = 2 (reference)
    distance L5 L11 = 10.414
    radius about axis L10 L1 = 5.08 {= Body3.DFS / 2}
    distance E5 P9 = 10.414 {= Body3.TFS - Body3.R}
    radius about axis P9 L1 = 5.08 {= (Body3.DFS / 2) - Body3.R}
    radius A1 = 0 (reference)
    angle L14 L15 = 0
    distance L2 P3 = 0
    length L2 = 3.5687 (reference)
    distance O P19 = 30
    distance P18 P19 V = 32 {= Sketch27.distance(O P19) + Body3.F1}
    coincidence: E4 L5, L1 E3, P11 P10, P12 L11, P19 L1
    perpendicularity: L1 L7, E2 L6, L12 L10, L13 L11
    symmetry: P4 P7 L1, L4 L9 L1, P3 P14 L1, P13 P15 L1, L14 L15 L1
  Groove3 "MainGroove": profile Sketch27, axis Sketch27.L1, angle 360
  Point20 "LimitingAxisSystemOrigin": type OnCurve, Support edge [ZX plane of AxisSystem14 | YZ plane of AxisSystem14], RefPoint Intersect2, Length 0 {= (Sketch27.length(L2)) * (Body3.Offset / Body3.Offset)}
  AxisSystem15 "LimitingAxisSystem": origin (36.195, 50.8, -209.55), X (-0.9916, -0.1291, 0), Y (0.1168, -0.8972, -0.4259), Z (0.055, -0.4224, 0.9048)
Body4 "UDF_Body"
  AxisSystem16 "MainAxisSystem": origin (-36.195, 50.8, -250.19), X (-0.9916, -0.1291, 0), Y (-0.1291, 0.9916, 0), Z (0, 0, -1)
  Project3 "Project": ToProject vertex [YZ plane of AxisSystem16 | ZX plane of AxisSystem16 | XY plane of AxisSystem16], Support face of RectPattern1
  Intersect3 "Intersect": ToIntersect1 edge [ZX plane of AxisSystem16 | YZ plane of AxisSystem16], ToIntersect2 face of RectPattern1
  Sketch28 "MainProfileSketch" on ZX plane of AxisSystem16, origin (-36.195, 50.8, -250.19), H (0.9916, 0.1291, 0), V (0, 0, -1)
    axis line L1 (0, 0) -> (0, -40.64)
    line L2 (0, -40.64) -> (3.5687, -40.64)
    point P3 (3.5687, -40.64)
    line L3 (3.5687, -40.64) -> (3.5687, -10.414)
    line L4 (5.08, -2) -> (7.08, 0)
    point P4 (7.08, 0)
    line L5 (7.08, 0) -> (7.08, 0)
    line L6 (7.08, 0) -> (7.08, 0)
    line L7 (7.08, 0) -> (0, 0)
    construction line L8 (7.08, 0) -> (0, 0)
    reference projected line E1 through (0, 0) direction (-1, 0) from edge [XY plane of AxisSystem16 | ZX plane of AxisSystem16]
    reference projected line E2 through (0, 0) direction (-1, 0) from edge [XY plane of AxisSystem16 | ZX plane of AxisSystem16]
    reference projected line E3 through (0, 0) direction (0, 1) from edge [ZX plane of AxisSystem16 | YZ plane of AxisSystem16]
    point P7 (-7.08, 0)
    construction line L9 (-11.04, 3.96) -> (-7.08, 0)
    reference projected line E4 through (0, 0) direction (-1, 0) from edge [XY plane of AxisSystem16 | ZX plane of AxisSystem16]
    line L10 (5.08, -10.414) -> (5.08, -2)
    line L11 (3.5687, -10.414) -> (5.08, -10.414)
    arc A1 centre (5.08, -10.414) radius 0 from (5.08, -10.414) to (5.08, -10.414) ccw
    point P9 (5.08, -10.414)
    reference projected line E5 through (0, 0) direction (-1, 0) from edge [XY plane of AxisSystem16 | ZX plane of AxisSystem16]
    construction line L12 (5.08, -10.414) -> (5.08, -10.414)
    construction line L13 (5.08, -10.414) -> (5.08, -10.414)
    point P10 (5.08, -10.414)
    point P11 (5.08, -10.414)
    point P12 (5.08, -10.414)
    line L14 (3.5687, -40.64) -> (3.5687, -40.64)
    point P13 (3.5687, -40.64)
    point P14 (-3.5687, -40.64)
    point P15 (-3.5687, -40.64)
    construction line L15 (-3.5687, -40.64) -> (-3.5687, -40.64)
    point P18 (5.08, -2)
    reference projected line E6 through (0, 0) direction (-1, 0) from edge [XY plane of AxisSystem16 | ZX plane of AxisSystem16]
    point P19 (0, 30)
    angle L4 L9 = 90
    radius about axis L1 L3 = 3.5687 {= Body4.DB / 2}
    distance E1 L2 = 40.64 {= Body4.Offset + (Sketch28.length(L2) * (Body4.Offset / Body4.Offset))}
    length L8 = 7.08 {= sqrt((Body4.AS_H * Body4.AS_H ) + ((Groove4.top_width / 2 + Groove4.AS_ZR ) * (Groove4.top_width / 2 + Groove4.AS_ZR )))}
    angle L8 L5 = 0 {= atan(Body4.AS_H / (Groove4.top_width / 2 + Groove4.AS_ZR ))}
    distance E6 P18 = 2 (reference)
    distance L5 L11 = 10.414
    radius about axis L10 L1 = 5.08 {= Body4.DFS / 2}
    distance E5 P9 = 10.414 {= Body4.TFS - Body4.R}
    radius about axis P9 L1 = 5.08 {= (Body4.DFS / 2) - Body4.R}
    radius A1 = 0 (reference)
    angle L14 L15 = 0
    distance L2 P3 = 0
    length L2 = 3.5687 (reference)
    distance O P19 = 30
    distance P18 P19 V = 32 {= Sketch28.distance(O P19) + Body4.F1}
    coincidence: E4 L5, L1 E3, P11 P10, P12 L11, P19 L1
    perpendicularity: L1 L7, E2 L6, L12 L10, L13 L11
    symmetry: P4 P7 L1, L4 L9 L1, P3 P14 L1, P13 P15 L1, L14 L15 L1
  Groove4 "MainGroove": profile Sketch28, axis Sketch28.L1, angle 360
  Point21 "LimitingAxisSystemOrigin": type OnCurve, Support edge [ZX plane of AxisSystem16 | YZ plane of AxisSystem16], RefPoint Intersect3, Length 0 {= (Sketch28.length(L2)) * (Body4.Offset / Body4.Offset)}
  AxisSystem17 "LimitingAxisSystem": origin (-36.195, 50.8, -209.55), X (-0.9916, -0.1291, 0), Y (0.1168, -0.8972, -0.4259), Z (0.055, -0.4224, 0.9048)
Body5 "UDF_Body"
  AxisSystem18 "MainAxisSystem": origin (-108.585, 50.8, -250.19), X (-0.9916, -0.1291, 0), Y (-0.1291, 0.9916, 0), Z (0, 0, -1)
  Project4 "Project": ToProject vertex [YZ plane of AxisSystem18 | ZX plane of AxisSystem18 | XY plane of AxisSystem18], Support face of RectPattern1
  Intersect4 "Intersect": ToIntersect1 edge [ZX plane of AxisSystem18 | YZ plane of AxisSystem18], ToIntersect2 face of RectPattern1
  Sketch29 "MainProfileSketch" on ZX plane of AxisSystem18, origin (-108.585, 50.8, -250.19), H (0.9916, 0.1291, 0), V (0, 0, -1)
    axis line L1 (0, 0) -> (0, -40.64)
    line L2 (0, -40.64) -> (3.5687, -40.64)
    point P3 (3.5687, -40.64)
    line L3 (3.5687, -40.64) -> (3.5687, -10.414)
    line L4 (5.08, -2) -> (7.08, 0)
    point P4 (7.08, 0)
    line L5 (7.08, 0) -> (7.08, 0)
    line L6 (7.08, 0) -> (7.08, 0)
    line L7 (7.08, 0) -> (0, 0)
    construction line L8 (7.08, 0) -> (0, 0)
    reference projected line E1 through (0, 0) direction (-1, 0) from edge [XY plane of AxisSystem18 | ZX plane of AxisSystem18]
    reference projected line E2 through (0, 0) direction (-1, 0) from edge [XY plane of AxisSystem18 | ZX plane of AxisSystem18]
    reference projected line E3 through (0, 0) direction (0, 1) from edge [ZX plane of AxisSystem18 | YZ plane of AxisSystem18]
    point P7 (-7.08, 0)
    construction line L9 (-11.04, 3.96) -> (-7.08, 0)
    reference projected line E4 through (0, 0) direction (-1, 0) from edge [XY plane of AxisSystem18 | ZX plane of AxisSystem18]
    line L10 (5.08, -10.414) -> (5.08, -2)
    line L11 (3.5687, -10.414) -> (5.08, -10.414)
    arc A1 centre (5.08, -10.414) radius 0 from (5.08, -10.414) to (5.08, -10.414) ccw
    point P9 (5.08, -10.414)
    reference projected line E5 through (0, 0) direction (-1, 0) from edge [XY plane of AxisSystem18 | ZX plane of AxisSystem18]
    construction line L12 (5.08, -10.414) -> (5.08, -10.414)
    construction line L13 (5.08, -10.414) -> (5.08, -10.414)
    point P10 (5.08, -10.414)
    point P11 (5.08, -10.414)
    point P12 (5.08, -10.414)
    line L14 (3.5687, -40.64) -> (3.5687, -40.64)
    point P13 (3.5687, -40.64)
    point P14 (-3.5687, -40.64)
    point P15 (-3.5687, -40.64)
    construction line L15 (-3.5687, -40.64) -> (-3.5687, -40.64)
    point P18 (5.08, -2)
    reference projected line E6 through (0, 0) direction (-1, 0) from edge [XY plane of AxisSystem18 | ZX plane of AxisSystem18]
    point P19 (0, 30)
    angle L4 L9 = 90
    radius about axis L1 L3 = 3.5687 {= Body5.DB / 2}
    distance E1 L2 = 40.64 {= Body5.Offset + (Sketch29.length(L2) * (Body5.Offset / Body5.Offset))}
    length L8 = 7.08 {= sqrt((Body5.AS_H * Body5.AS_H ) + ((Groove5.top_width / 2 + Groove5.AS_ZR ) * (Groove5.top_width / 2 + Groove5.AS_ZR )))}
    angle L8 L5 = 0 {= atan(Body5.AS_H / (Groove5.top_width / 2 + Groove5.AS_ZR ))}
    distance E6 P18 = 2 (reference)
    distance L5 L11 = 10.414
    radius about axis L10 L1 = 5.08 {= Body5.DFS / 2}
    distance E5 P9 = 10.414 {= Body5.TFS - Body5.R}
    radius about axis P9 L1 = 5.08 {= (Body5.DFS / 2) - Body5.R}
    radius A1 = 0 (reference)
    angle L14 L15 = 0
    distance L2 P3 = 0
    length L2 = 3.5687 (reference)
    distance O P19 = 30
    distance P18 P19 V = 32 {= Sketch29.distance(O P19) + Body5.F1}
    coincidence: E4 L5, L1 E3, P11 P10, P12 L11, P19 L1
    perpendicularity: L1 L7, E2 L6, L12 L10, L13 L11
    symmetry: P4 P7 L1, L4 L9 L1, P3 P14 L1, P13 P15 L1, L14 L15 L1
  Groove5 "MainGroove": profile Sketch29, axis Sketch29.L1, angle 360
  Point22 "LimitingAxisSystemOrigin": type OnCurve, Support edge [ZX plane of AxisSystem18 | YZ plane of AxisSystem18], RefPoint Intersect4, Length 0 {= (Sketch29.length(L2)) * (Body5.Offset / Body5.Offset)}
  AxisSystem19 "LimitingAxisSystem": origin (-108.585, 50.8, -209.55), X (-0.9916, -0.1291, 0), Y (0.1168, -0.8972, -0.4259), Z (0.055, -0.4224, 0.9048)
Relations
  Body2.W1 = Sketch26.angle(L4 L9)
  Body2.W3 = Sketch26.angle(L14 L15)
  Body2.TFS = Sketch26.distance(L5 L11)
  Body2.T = Sketch26.distance(E1 L2)
  Body2.F3 = Sketch26.distance(L2 P3)
  Groove2.top_width = (`Sketch26.radius about axis(L10 L1)` * 2) + (2 * tan(Sketch26.angle(L4 L9) / 2) * Sketch26.distance(E6 P18) )
  rule "AS_ZR":
    /*Rule created by AKNOPP 22.05.2006*/
    Groove2.AS_ZR = Body2.AS_D - Groove2.top_width
    if (Body2.AS_D == 0mm)
    {
    	Groove2.AS_ZR = 0mm
    }
    else
    {
    	Groove2.AS_ZR = (Body2.AS_D / 2) - (Groove2.top_width / 2)
    }
  Body3.W1 = Sketch27.angle(L4 L9)
  Body3.W3 = Sketch27.angle(L14 L15)
  Body3.TFS = Sketch27.distance(L5 L11)
  Body3.T = Sketch27.distance(E1 L2)
  Body3.F3 = Sketch27.distance(L2 P3)
  Groove3.top_width = (`Sketch27.radius about axis(L10 L1)` * 2) + (2 * tan(Sketch27.angle(L4 L9) / 2) * Sketch27.distance(E6 P18) )
  rule "AS_ZR":
    /*Rule created by AKNOPP 22.05.2006*/
    Groove3.AS_ZR = Body3.AS_D - Groove3.top_width
    if (Body3.AS_D == 0mm)
    {
    	Groove3.AS_ZR = 0mm
    }
    else
    {
    	Groove3.AS_ZR = (Body3.AS_D / 2) - (Groove3.top_width / 2)
    }
  Body4.W1 = Sketch28.angle(L4 L9)
  Body4.W3 = Sketch28.angle(L14 L15)
  Body4.TFS = Sketch28.distance(L5 L11)
  Body4.T = Sketch28.distance(E1 L2)
  Body4.F3 = Sketch28.distance(L2 P3)
  Groove4.top_width = (`Sketch28.radius about axis(L10 L1)` * 2) + (2 * tan(Sketch28.angle(L4 L9) / 2) * Sketch28.distance(E6 P18) )
  rule "AS_ZR":
    /*Rule created by AKNOPP 22.05.2006*/
    Groove4.AS_ZR = Body4.AS_D - Groove4.top_width
    if (Body4.AS_D == 0mm)
    {
    	Groove4.AS_ZR = 0mm
    }
    else
    {
    	Groove4.AS_ZR = (Body4.AS_D / 2) - (Groove4.top_width / 2)
    }
  Body5.W1 = Sketch29.angle(L4 L9)
  Body5.W3 = Sketch29.angle(L14 L15)
  Body5.TFS = Sketch29.distance(L5 L11)
  Body5.T = Sketch29.distance(E1 L2)
  Body5.F3 = Sketch29.distance(L2 P3)
  Groove5.top_width = (`Sketch29.radius about axis(L10 L1)` * 2) + (2 * tan(Sketch29.angle(L4 L9) / 2) * Sketch29.distance(E6 P18) )
  rule "AS_ZR":
    /*Rule created by AKNOPP 22.05.2006*/
    Groove5.AS_ZR = Body5.AS_D - Groove5.top_width
    if (Body5.AS_D == 0mm)
    {
    	Groove5.AS_ZR = 0mm
    }
    else
    {
    	Groove5.AS_ZR = (Body5.AS_D / 2) - (Groove5.top_width / 2)
    }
